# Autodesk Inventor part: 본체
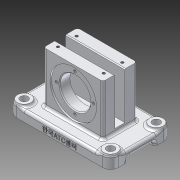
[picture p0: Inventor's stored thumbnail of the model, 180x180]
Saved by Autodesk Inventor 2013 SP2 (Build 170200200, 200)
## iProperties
Created: 2025-04
Part Number: 본체
Material: 알루미늄 6061
Document SubType Name: Modeling
Designer: 601
Density: 2.71 g/cm^3
Mass: 496.284 g
Surface Area: 439.939 cm^2
Volume: 183.131 cm^3
Author: 601
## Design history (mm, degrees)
sketch "스케치1"
  geometry: L1 (-35, 30)-(35, 30); L2 (35, 30)-(35, -42); L3 (35, -42)-(-35, -42); L4 (-35, -42)-(-35, 30); 2 further points
  constraints: 8 end point, 2 parallel, 1 horizontal, 1 midpoint, 1 perpendicular, 1 vertical alignment
  dimensions: "d0" = 72 distance between parallel lines of L3 L1; "d2" = 42 distance from line of L3 point (0, 0); "d3" = 70 distance of L2.end L3.end
extrude "돌출1" new body sketch "스케치1" stored distance "d4" = 40; taper "d5" = 0 deg
sketch "스케치2"
  geometry: L1 (-25, 16)-(95, 16); L2 (95, 16)-(95, -56); L3 (95, -56)-(-25, -56); L4 (-25, -56)-(-25, 16); L5 (-25, 16)-(95, -56); L6 (95, 16)-(-25, -56); 1 further point
  constraints: 12 end point, 2 midpoint, 2 parallel, 1 horizontal, 1 perpendicular
  dimensions: "d6" = 72 distance of L1.end L2.end; "d8" = 120 distance of L2.end L3.end
extrude "돌출2" join sketch "스케치2" distance "d9" = 12; taper "d10" = 0 deg
fillet "모깎기1" dims "d11" = 9
sketch "스케치3"
  geometry: L1 (0, 0)-(54, 0) reference; L2 (11, 5)-(43, 5); L3 (43, 5)-(43, 0); L4 (43, 0)-(11, 0); L5 (11, 0)-(11, 5); 2 further points
  constraints: 8 end point, 2 midpoint, 2 parallel, 1 horizontal, 1 perpendicular
  dimensions: "d12" = 32 distance between parallel lines of L3 L5; "d14" = 5 distance between parallel lines of L1 L2
extrude "돌출3" cut sketch "스케치3" stored distance "d15" = 12; taper "d16" = 0 deg
sketch "스케치4"
  geometry: L1 (0, 0)-(40, 0) reference; L2 (14, 0)-(26, 0); L3 (26, 0)-(26, -55); L4 (26, -55)-(14, -55); L5 (14, -55)-(14, 0); 2 further points
  constraints: 8 end point, 2 midpoint, 2 parallel, 1 horizontal, 1 perpendicular
  dimensions: "d17" = 12 distance between parallel lines of L3 L5; "d19" = 55 distance between parallel lines of L4 L1
extrude "돌출4" cut sketch "스케치4" stored distance "d20" = 12; taper "d21" = 0 deg
sketch "스케치5"
  geometry: C1 r 8 at (-16, 47); A1 r 9 centre (-16, 47) between (-16, 56) and (-25, 47) reference; 1 further point
  constraints: 1 centre point, 1 coincident
  dimensions: "d22" = 16 diameter of C1
extrude "돌출5" join sketch "스케치5" distance "d23" = 3; taper "d24" = 0 deg
sketch "스케치6"
  geometry: C1 r 8 at (0, 0) reference; C2 r 4.5 at (0, 0); 1 further point
  constraints: 1 centre point, 1 coincident
  dimensions: "d25" = 9 diameter of C2
extrude "돌출6" cut sketch "스케치6" distance "d26" = 15; taper "d27" = 0 deg
sketch "스케치7"
  geometry: C1 r 17 at (0, 0); 1 further point
  constraints: 1 centre point, 1 coincident
  dimensions: "d28" = 34 diameter of C1
extrude "돌출7" join sketch "스케치7" distance "d29" = 7; taper "d30" = 0 deg
sketch "스케치8"
  geometry: C1 r 27.5 at (0, 0); 1 further point
  constraints: 1 centre point, 1 coincident
  dimensions: "d31" = 55 diameter of C1
extrude "돌출8" cut sketch "스케치8" distance "d32" = 2; taper "d33" = 0 deg
sketch "스케치9"
  geometry: C1 r 27.5 at (0, 0) reference; C2 r 18 at (0, 0)
  constraints: 1 centre point, 1 coincident
  dimensions: "d34" = 36 diameter of C2
extrude "돌출9" cut sketch "스케치9" stored distance "d35" = 36 (= d34); taper "d36" = 0 deg
sketch "스케치10"
  geometry: C1 r 17 at (0, 0) reference; C2 r 11 at (0, 0)
  constraints: 1 centre point, 1 coincident
  dimensions: "d37" = 22 diameter of C2
extrude "돌출10" cut sketch "스케치10" stored distance "d38" = 2; taper "d39" = 0 deg
sketch "스케치11"
  geometry: C1 r 11 at (-35, 25) reference; C2 r 15 at (-35, 25)
  constraints: 1 centre point, 1 coincident
  dimensions: "d40" = 30 diameter of C2
extrude "돌출11" cut sketch "스케치11" distance "d41" = 5; taper "d42" = 0 deg
chamfer "모따기1" distance "d43" = 1; stored, may be unused: second distance "d44" = 2, angle "d45" = 45 deg
sketch "스케치12" dims "d46" = 44
  geometry: C1 r 19 at (0, 0) reference; 2 further points
  constraints: 2 vertical alignment, 1 coincident, 2 other
hole "구멍1" sketch "스케치12" at (0, 22) diameter "d47" = 3.242; stored, may be unused: countersink angle "d51" = 90 deg, drill point angle "d53" = 118 deg; dims "d48" = 8, "d49" = 4, "d50" = 2, "d52" = 10
fillet "모깎기2" dims "d57" = 3
chamfer "모따기2" distance "d58" = 1; stored, may be unused: second distance "d59" = 2, angle "d60" = 45 deg
fillet "모깎기3" dims "d61" = 3
fillet "모깎기4" dims "d62" = 3
fillet "모깎기5" dims "d63" = 3
fillet "모깎기6" dims "d64" = 3
sketch "스케치13"
  geometry: L1 (59, -31)-(5, -31); L2 (5, -31)-(5, -9); L3 (5, -9)-(59, -9); L4 (59, -9)-(59, -31); L5 (59, -31)-(5, -9); L6 (5, -31)-(59, -9); 5 further points
  constraints: 12 end point, 4 coincident, 2 midpoint, 2 parallel, 1 horizontal, 1 perpendicular
  dimensions: "d65" = 54 distance between parallel lines of L4 L2; "d67" = 22 distance between parallel lines of L1 L3
hole "구멍2" sketch "스케치13" at (5, -9), (59, -9), (59, -31), (5, -31) diameter "d68" = 3.242; stored, may be unused: countersink angle "d72" = 90 deg, drill point angle "d74" = 118 deg; dims "d69" = 8, "d70" = 4, "d71" = 2, "d73" = 10
node "작업 평면1"
sketch "스케치14"
  geometry: L1 (111, 0)-(102, 0) reference; 2 further points
  constraints: 1 vertical alignment, 1 other
  dimensions: "d76" = 5 distance from line of L1 point (51, 5)
feature "엠보싱1" sketch "스케치14" dims "d0" = 72, "d2" = 42, "d3" = 70, "d77" = 0.5, "d78" = 0
fillet "모깎기7" dims "d79" = 3
fillet "모깎기8" dims "d80" = 3
node "솔리드1"
mirror "대칭1"
mirror "대칭2"
pattern_circular "원형 패턴1" dims angle "d55" = 360 deg
other parameters: "d75" = 8.25
